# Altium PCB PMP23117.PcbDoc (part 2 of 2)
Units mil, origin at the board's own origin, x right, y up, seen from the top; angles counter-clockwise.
Board outline 3300 x 2800 mil, 6 copper layers (Top Layer, GND Layer 1, Signal Layer 1, GND Layer 2, Signal Layer3, Bottom Layer), stack 62.8 mil thick; 125 components, 38 nets, 250 pads, 683 vias.
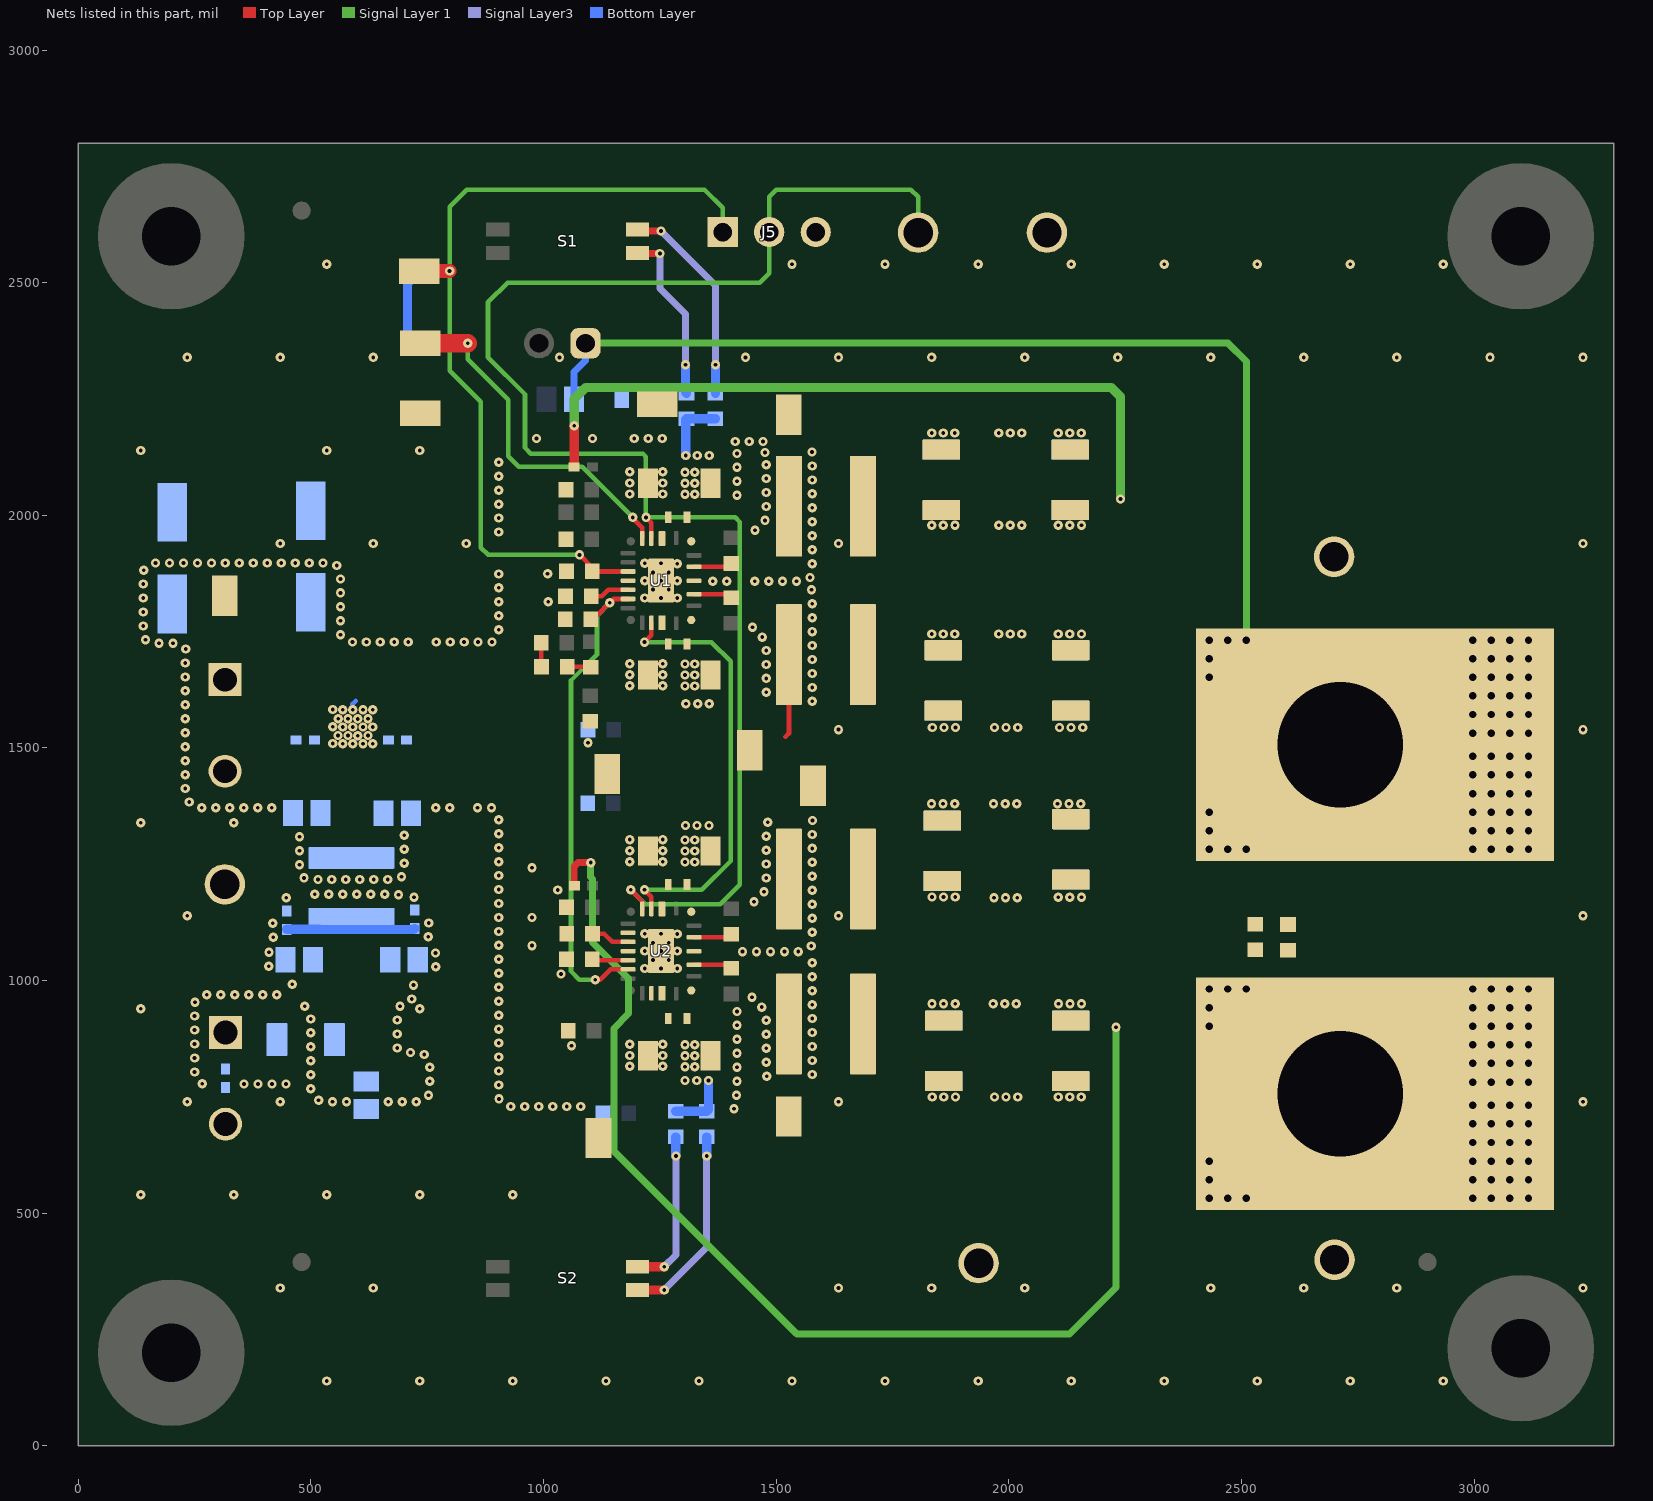
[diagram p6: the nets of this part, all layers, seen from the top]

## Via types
v1: diameter 20, hole 8, Top Layer to Bottom Layer, tented both sides, 561 vias
v2: diameter 32, hole 16, Top Layer to Bottom Layer, 116 vias
v3: diameter 19.68, hole 7.87, Top Layer to Bottom Layer, 6 vias

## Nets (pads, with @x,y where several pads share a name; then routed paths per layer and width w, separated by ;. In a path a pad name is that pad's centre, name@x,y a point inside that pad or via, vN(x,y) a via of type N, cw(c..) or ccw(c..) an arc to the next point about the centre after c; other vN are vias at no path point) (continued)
GND: C1.2 C2.2 C3.1 C4.1 C5.2 C6.2 C8.1 C9.1 C10.1 C11.1 C12.1 C13.2 C14.1 C15.1 C18.1 C19.1 C20.1 C21.1 C22.1 C23.2 C24.1 C25.1 C26.2 C27.1 C28.1 C29.2 C30.2 C32.1 C33.1 C34.1 C35.1 C36.1 C37.1 C38.1 C40.1 C45.2 C46.2 C47.2 C48.2 C49.2 C50.2 C51.2 C52.2 C53.2 C54.2 J1.2 J3.1 J5.3 J6.2 R6.1 R7.1 R10.1 R12.1 R14.1 R16.1 R17.1 R20.1 R23.1 T2.1 TP11.1 TP12.1 TP13.1 TP14.1 TP15.1 TP16.1 TP17.1 TP18.1 U1.4 U1.9 U1.16 U1.23 U1.25 U2.4 U2.9 U2.14 U2.16 U2.23 U2.25 | length 51.7
  Top Layer w10: C26.2@1050.61,1674.35 1100.66,1674.35 C24.1@1101.8,1673.2
  other v1: 534,139.5 734,139.5 934,139.5 1134,139.5 1334,139.5 1534,139.5 1734,139.5 1934,139.5 2134,139.5 2334,139.5 2534,139.5 2734,139.5 2934,139.5 434,339.5 634,339.5 1634,339.5 1834,339.5 2034,339.5 2434,339.5 2634,339.5 2834,339.5 3234,339.5 134,539.5 334,539.5 534,539.5 734,539.5 934,539.5 1409.2,724.28 929.63,729.61 959.63,729.61 989.63,729.61 1019.63,729.61 1049.63,729.61 1079.63,729.61 234,739.5 434,739.5 546.27,739.61 576.27,739.61 666.27,739.61 696.27,739.61 726.27,739.61 1634,739.5 3234,739.5 516.43,742.75 904.35,745.76 1835.55,750 1860.37,750 1885.37,750 1969.17,750 1994,750 2019,750 2106.11,750 2130.94,750 2155.94,750 752.7,753.8 1414.73,753.76 499.68,767.64 903.61,775.75 356.14,777.7 386.14,777.7 416.14,777.7 446.14,777.7 266.15,778.53 755.39,783.67 1415.89,783.74 1479.72,794.57 499.61,797.64 1577.19,798.36 249.91,803.75 903.61,805.75 755.39,813.67 1415.89,813.74 1185,815.65 1256.07,815.65 1478.57,824.55 499.61,827.64 1577.19,828.36 249.91,833.75 903.61,835.75 1185,839.13 1256.07,839.13 743.45,841.2 1415.89,843.74 713.75,845.39 1478.57,854.55 685.39,855.19 499.61,857.64 1577.19,858.36 1060,860.17 249.91,863.75 1185,863.05 1256.07,863.05 903.61,865.75 1415.89,873.74 1478.57,884.55 685.39,885.19 499.61,887.64 1577.19,888.36 249.91,893.75 903.61,895.75 1415.89,903.74 1478.57,914.55 685.39,915.19 499.61,917.64 1577.19,918.36 249.91,923.75 903.61,925.75 1415.89,933.74 134,939.5 734,939.5 1469.19,943.04 486.92,944.82 691.27,944.61 1577.19,948.36 250.82,953.74 903.61,955.75 716.67,960.57 1447.98,964.26 276.29,969.58 306.29,969.58 336.29,969.58 366.29,969.58 396.29,969.58 426.29,969.58 1577.19,978.36 903.61,985.75 720.39,990.34 459.61,992.01 1577.19,1008.36 1037.49,1014 903.61,1015.75 1217.22,1026.08 1287.22,1026.08 768.23,1029.78 409,1031 1577.19,1038.36 1235.22,1044.51 1269.22,1044.51 903.61,1045.75 767.86,1059.4 410,1061 1427.64,1062.34 1457.64,1062.34 1487.64,1062.34 1517.64,1062.34 1547.64,1062.34 1217.22,1063.48 1287.22,1063.48 1575.18,1074.24 903.61,1075.75 975,1075.23 1235.22,1081.25 1269.22,1081.25 418.84,1093.12 751.94,1094.02 1217.22,1100.88 1287.22,1100.01 1577.19,1104.18 903.61,1105.75 417.96,1123.11 753.23,1123.99 1577.19,1134.18 903.61,1135.75 975,1135.75 234,1139.5 1634,1139.5 3234,1139.5 1577.19,1164.18 903.61,1165.75 1452.41,1169.66 446.89,1178 721.43,1179.23 688.36,1184.62 508.37,1185.46 538.37,1185.39 568.37,1185.39 598.37,1185.39 628.37,1185.39 658.37,1185.39 1473.62,1190.87 1030.27,1194.79 1577.19,1194.18 903.61,1195.75 514.96,1217.32 544.96,1217.32 574.96,1217.32 604.96,1217.32 634.96,1217.32 664.96,1217.32 485.16,1220.77 1478.68,1220.44 694.4,1223.07 1577.19,1224.18 903.61,1225.75 975,1242.81 475.41,1249.14 1478.68,1250.44 700.71,1252.4 1577.19,1254.18 903.61,1255.75 1185,1255.65 1256.07,1255.65 475.41,1279.14 1185,1279.13 1256.07,1279.13 1478.68,1280.44 700.71,1282.4 1577.19,1284.18 903.61,1285.75 1185,1303.05 1256.07,1303.05 475.41,1309.14 1478.68,1310.44 700.71,1312.4 1577.19,1314.18 903.61,1315.75 134,1339.5 334,1339.5 1481.72,1340.29 1578,1344 903.61,1345.75 265.5,1371.46 295.5,1371.46 325.5,1371.46 355.5,1371.46 385.5,1371.46 415.5,1371.46 768.16,1371.46 798.16,1371.46 858.16,1371.46 888.16,1371.46 1833.69,1380 1858.51,1380 1883.51,1380 1967.17,1380 1992,1380 2017,1380 2104.69,1380 2129.51,1380 2154.51,1380 238.24,1383.99 229.61,1412.72 229.61,1442.72 229.61,1472.72 229.61,1502.72 1095.33,1511.21 229.61,1532.72 1634,1539.5 3234,1539.5 1835.69,1543.96 1860.51,1543.96 1885.51,1543.96 1969.17,1543.96 1994,1543.96 2019,1543.96 2108.79,1543.96 2133.62,1543.96 2158.62,1543.96 229.61,1562.72 229.61,1592.72 1577.19,1600.14 1478.68,1619.57 229.61,1622.72 1577.19,1630.14 1185,1633.93 1256.07,1633.93 1478.68,1649.57 229.61,1652.72 1185,1657.41 1256.07,1657.41 1577.19,1660.14 1478.68,1679.57 1185,1681.33 1256.07,1681.33 229.61,1682.72 1577.19,1690.14 1478.68,1709.57 230.77,1712.7 1577.19,1720.14 173.49,1725.28 203.49,1725.17 589.16,1727.82 619.16,1727.82 649.16,1727.82 679.16,1727.82 709.16,1727.82 769.16,1727.82 799.16,1727.82 829.16,1727.82 859.16,1727.82 889.16,1727.82 144.42,1732.72 1470.07,1738.31 563.48,1743.33 1577.19,1750.14 903.61,1754.11 1448.85,1759.52 139.41,1762.3 563.48,1773.33 1577.19,1780.14 903.61,1784.11 139.41,1792.3 563.48,1803.33 1577.19,1810.14 903.61,1814.11 1010.25,1814.35 139.41,1822.3 1217.22,1822.23 1287.22,1822.23 563.48,1833.33 1235.22,1840.66 1269.22,1840.66 1575.84,1840.11 903.61,1844.11 139.41,1852.3 1363.7,1858.49 1393.7,1858.49 1453.7,1858.49 1483.7,1858.49 1513.7,1858.49 1543.7,1858.49 1217.22,1859.63 1287.22,1859.63 563.48,1863.33 1572.6,1866.53 903.61,1874.11 1008.64,1874.25 1235.22,1877.4 1269.22,1877.4 140.38,1882.29 555.55,1892.27 1287.22,1896.16 1577.19,1896.18 166.06,1897.79 196.06,1897.79 226.06,1897.79 256.06,1897.79 286.06,1897.79 316.06,1897.79 346.06,1897.79 376.06,1897.79 406.06,1897.79 436.06,1897.79 466.06,1897.79 496.06,1897.79 526.06,1897.79 1217.22,1897.03 1577.19,1926.18 434,1939.5 634,1939.5 834,1939.5 1634,1939.5 3234,1939.5 1577.19,1956.18 903.61,1964.11 1454.55,1967.95 1577.19,1986.18 1475.77,1989.16 903.61,1994.11 1577.19,2016.18 1478.68,2019.02 903.61,2024.11 1415.89,2043.14 1185,2046.04 1256.07,2046.04 1577.19,2046.18 1478.68,2049.02 903.61,2054.11 1185,2069.53 1256.07,2069.53 1415.89,2073.14 1577.19,2076.18 1478.68,2079.02 903.61,2084.11 1185,2093.44 1256.07,2093.44 1415.89,2103.14 1577.19,2106.18 1478.68,2109.02 903.61,2114.11 1415.89,2133.14 1476,2135 1577,2136 134,2139.5 534,2139.5 734,2139.5 1411.79,2158.81 1441.79,2158.81 1471.79,2158.81 984.95,2165.25 1104.95,2165.25 1194.95,2165.25 1224.95,2165.25 1254.95,2165.25 1834.03,2177 1858.86,2177 1883.86,2177 1978.17,2177 2003,2177 2028,2177 2105.93,2177 2130.76,2177 2155.76,2177 234,2339.5 434,2339.5 634,2339.5 1034,2339.5 1434,2339.5 1634,2339.5 1834,2339.5 2034,2339.5 2234,2339.5 2434,2339.5 2634,2339.5 2834,2339.5 3034,2339.5 3234,2339.5 534,2539.5 1534,2539.5 1734,2539.5 1934,2539.5 2134,2539.5 2334,2539.5 2534,2539.5 2734,2539.5 2934,2539.5
  other v2: 2430.73,532 2470.73,532 2510.73,532 2997,532 3037,532 3077,532 3117,532 2430.73,572 2997,572 3037,572 3077,572 3117,572 2430.73,612 2997,612 3037,612 3077,612 3117,612 2997,652 3037,652 3077,652 3117,652 2997,692 3037,692 3077,692 3117,692 2997,732 3037,732 3077,732 3117,732 2997,782 3037,782 3077,782 3117,782 2997,822 3037,822 3077,822 3117,822 2997,862 3037,862 3077,862 3117,862 2430.73,902 2997,902 3037,902 3077,902 3117,902 2430.73,942 2997,942 3037,942 3077,942 3117,942 2430.73,982 2470.73,982 2510.73,982 2997,982 3037,982 3077,982 3117,982
  other v3: 1252.43,1026.08 1252.43,1063.48 1252.43,1100.88 1252.43,1822.23 1252.43,1859.63 1252.43,1897.03
MODE: J5.2 TP5.1 U1.10 U2.11 | length 3296.5
  Top Layer w10: v1@1182.41,1195.05 v1(1187.1,1195.05) 1212.07,1170.08 U2.11@1212.07,1154.03 ; v1@1226.8,1988.88 1231.76,1983.92 U1.10@1231.76,1950.18
  Signal Layer 1 w10: v1(1187.1,1195.05) 1218.28,1163.88 1380.03,1163.88 1421.88,1205.73 1421.88,1985.75 1412.02,1995.61 v1(1219.95,1995.61) 1219.95,2126 1213.71,2132.24 972.76,2132.24 960,2145 960,2260 880.39,2339.61 880.39,2457.89 922.51,2500 1464.79,2500 1484.95,2520.16 J5.2@1484.95,2608.88 1484.95,2684.95 1500,2700 1789.38,2700 1805,2684.38 TP5.1@1805,2607.75
NetC26_1: C26.1 R13.1 | length 52.1
  Top Layer w10: R13.1@994.76,1726.13 994.76,1675.08 C26.1@995.49,1674.35
NetR2_2: R2.2 S1.1 | length 372.7
  Top Layer w15: S1.1@1201.68,2564.19 1203.06,2562.8 v1(1250,2562.8)
  Signal Layer3 w15: v1(1250,2562.8) 1250,2487.43 1304.91,2432.51 v1(1304.91,2323.55)
  Bottom Layer w20: v1(1304.91,2323.55) 1304.91,2264.85 R2.2@1307.1,2262.67
NetR5_2: R5.2 S1.2 | length 449.1
  Top Layer w15: S1.2@1201.68,2614.19 1204.88,2610.99 v1(1252.43,2610.99)
  Signal Layer3 w15: v1(1252.43,2610.99) 1369.67,2493.74 v1(1369.67,2323.55)
  Bottom Layer w20: R5.2@1369.32,2262.67 1369.67,2263.02 v1(1369.67,2323.55)
NetR9_2: R9.2 S2.1 | length 424.5
  Top Layer w20: S2.1@1201.68,335 v1(1259.23,335)
  Signal Layer3 w15: v1(1259.23,335) 1350.42,426.19 v1(1350.42,622.81)
  Bottom Layer w20: v1(1350.42,622.81) 1350.42,663.7 R9.2@1350.73,664.02
NetR11_2: R11.2 S2.2 | length 347.1
  Top Layer w20: S2.2@1201.68,385 v1(1259.23,385)
  Signal Layer3 w15: v1(1259.23,385) 1284.42,410.19 v1(1284.42,622.81)
  Bottom Layer w20: R11.2@1284.29,664.02 1284.29,622.95 v1(1284.42,622.81)
PG1_P: R8.2 TP10.1 U1.11 | length 801.7
  Top Layer w10: v1(1191.8,1995.61) 1191.8,1994.05 1212.07,1973.78 U1.11@1212.07,1950.18
  Top Layer w40: TP10.1@765,2370 v1(837.27,2370)
  Signal Layer 1 w10: v1(837.27,2370) 837.27,2335.24 924,2248.51 924,2127.49 946.87,2104.63 1082.77,2104.63 v1(1191.8,1995.61)
  Bottom Layer w20: R8.2@762.55,2370 v1(837.27,2370)
RT_P: R10.2 U1.17 | length 85
  Top Layer w10: R10.2@1102.35,1825.93 1125.1,1825.93 1139.12,1839.94 U1.17@1181.56,1839.94
RT_S: R16.2 U2.17 | length 77.8
  Top Layer w10: R16.2@1104.36,1042.29 1105.86,1043.8 U2.17@1181.56,1043.8
SS: C25.2 U1.18 U2.18 | length 1064.5
  Top Layer w10: C25.2@1101.51,1776.95 1106.52,1776.95 1149.83,1820.26 U1.18@1181.56,1820.26 ; v1(1111.25,1001.68) 1121.54,1001.68 1143.97,1024.11 U2.18@1181.56,1024.11
  Signal Layer 1 w10: v1(1111.25,1001.68) 1076.98,1001.68 1058.89,1019.76 1058.89,1645 1114.91,1701.01 1114.91,1784.67 v1(1142.47,1812.23)
SW1: C7.2 L1.1 TP2.1 U1.5 | length 102.5
  Top Layer w10: U1.5@1323.29,1889.16 1396.84,1889.16 C7.2@1403.18,1895.49 ; TP2.1@1513.24,2206.76 TP2.1@1527.39,2192.61
SW2: C17.1 L2.1 TP4.1 U1.3 | length 262.7
  Top Layer w10: U1.3@1323.29,1830.1 1396.29,1830.1 C17.1@1403.18,1823.21 ; 1520,1523.88 1527.39,1531.26 L2.1@1527.39,1700.76
SW3: C31.1 L3.1 TP6.1 U2.5 | length 81.3
  Top Layer w10: U2.5@1323.29,1093.01 1399.87,1093.01 C31.1@1403.18,1096.32
SW4: C39.2 L4.1 TP8.1 U2.3 | length 107.4
  Top Layer w10: U2.3@1323.29,1033.95 1395.66,1033.95 C39.2@1403.18,1026.44 ; TP8.1@1510,708.57 TP8.1@1527.27,725.84
SYNCOUT: U1.22 U2.10 | length 937.4
  Top Layer w10: v1(1216.8,1195.05) 1231.76,1180.09 U2.10@1231.76,1154.03 ; v1(1217.04,1727.58) 1231.76,1742.3 U1.22@1231.76,1769.08
  Signal Layer 1 w10: v1(1216.8,1195.05) 1340,1195.05 1402,1257.05 1402,1686.34 1360.76,1727.58 v1(1217.04,1727.58) v1@1216.8,1727.34
SYNCOUT_S: U2.22
VCC_P: C15.2 J5.1 R8.1 TP7.1 U1.15 | length 2068.5
  Top Layer w10: v1(1077.3,1915) 1104.36,1887.94 C15.2@1104.36,1880.26 1105.3,1879.31 U1.15@1181.56,1879.31
  Top Layer w30: TP7.1@733.04,2525 v1(798,2525)
  Signal Layer 1 w10: v1(1077.3,1915) 880.62,1915 865,1930.62 865,2244 798,2311 v1(798,2525) 798,2663 835,2700 1345.93,2700 1384.95,2660.98 J5.1@1384.95,2608.88
  Bottom Layer w20: R8.1@707.44,2370 707.44,2499.4 733.04,2525 v1(798,2525)
VCC_S: C38.2 U2.15 | length 83.7
  Top Layer w10: C38.2@1105.15,1100.88 1129.79,1100.88 1147.51,1083.17 U2.15@1181.56,1083.17
VIN: C1.1 C2.1 C3.2 C4.2 C5.1 C6.1 C27.2 C28.2 C29.1 C30.1 C51.1 C52.1 C53.1 C54.1 J1.1 L5.2 R2.1 R5.1 R9.1 R11.1 TP1.1 U1.1 U1.7 U2.1 U2.7 | length 292.4
  Bottom Layer w10: J1.1@315.37,1646.85 J1.1@320,1651.48 ; 589,1594 596,1601
  Bottom Layer w20: R11.1@1284.29,719.13 R9.1@1350.73,719.13 1354.44,722.84 v1(1354.44,785.14) ; v1(1305.41,2128.48) 1305.41,2205.86 R2.1@1307.1,2207.55 R5.1@1369.32,2207.55
  other v1: 1303.94,785.14 1329.44,785.14 1303.94,815 1325,815 1303.94,838.48 1325,838.48 1303.94,862.4 1325,862.4 1303.94,1255 1325,1255 1303.94,1278.48 1325,1278.48 1303.94,1302.4 1325,1302.4 1304.91,1333.48 1329.91,1333.48 1355.41,1333.48 546.98,1509.5 568.5,1509 590,1509 611.87,1509 633,1509 600.5,1526.5 558.12,1527 579.5,1527 622.5,1527 546.98,1545.5 568.5,1545 590,1545 611.87,1545 633,1545 600.75,1562.5 558.37,1563 579.75,1563 622.75,1563 568.5,1582 590,1582 611.87,1582 633,1582 546.98,1582.5 1305.86,1595 1331.36,1595 1356.36,1595 1303.94,1633.28 1325,1633.28 1303.94,1656.76 1325,1656.76 1303.94,1680.68 1325,1680.68 1303.94,2045.39 1325,2045.39 1303.94,2068.88 1325,2068.88 1303.94,2092.8 1325,2092.8 1330.41,2128.48 1355.91,2128.48
VIN_EMI: C45.1 FB2.1 J6.1
VINEMI2: C46.1 C47.1 C48.1 C49.1 C50.1 FB2.2 L5.1 | length 276
  Bottom Layer w20: C48.1@448,1110.32 517.68,1110.32 518,1110 721,1110 C47.1@723,1112
VOUT: C8.2 C9.2 C10.2 C11.2 C12.2 C13.1 C18.2 C19.2 C20.2 C21.2 C22.2 C23.1 C32.2 C33.2 C34.2 C35.2 C36.2 C40.2 J2.1 J4.1 L1.2 L2.2 L3.2 L4.2 R1.2 R4.2 R15.1 T1.1 TP3.1 | length 6314.6
  Top Layer w15: R15.1@1065.92,1203.88 1065.92,1245.6 1073.95,1253.62 v1(1101.18,1253.62)
  Top Layer w20: R1.2@1065.92,2104.87 v1(1065.92,2192.61)
  Signal Layer 1 w15: J4.1@1090.05,2370 2471,2370 2510.53,2330.47 T1.1@2510.53,1732.4 ; v1(1101.18,1253.62) 1101.18,1222.72 1105.29,1218.61 1105.29,1081.71 1182.78,1004.23 1182.78,929.11 1150.93,897.26 1150.93,633.24 1544.17,240 2130.42,240 2230.42,340 v1(2230.42,900)
  Signal Layer 1 w20: v1(1065.92,2192.61) 1065.92,2250.36 1090.56,2275 2219.92,2275 2240,2254.92 v1(2240,2035.23)
  Bottom Layer w15: R4.2@1065.37,2249.81 1065.37,2307.88 1090.05,2332.56 J4.1@1090.05,2370
  other v1: 1834.78,950 1859.61,950 1884.61,950 1966.17,950 1991,950 2016,950 2106.54,950 2131.37,950 2156.37,950 1968.17,1178 1993,1178 2018,1178 1834.9,1179.75 1859.73,1179.75 1884.73,1179.75 2106.17,1179.23 2131,1179.23 2156,1179.23 1834.02,1745 1858.85,1745 1883.85,1745 1978.17,1745 2003,1745 2028,1745 2106.17,1745 2131,1745 2156,1745 1834.27,1979 1859.1,1979 1884.1,1979 1978.17,1979 2003,1979 2028,1979 2106.17,1979 2131,1979 2156,1979
  other v2: 2430.73,1282 2470.73,1282 2510.73,1282 2997,1282 3037,1282 3077,1282 3117,1282 2430.73,1322 2997,1322 3037,1322 3077,1322 3117,1322 2430.73,1362 2997,1362 3037,1362 3077,1362 3117,1362 2997,1402 3037,1402 3077,1402 3117,1402 2997,1442 3037,1442 3077,1442 3117,1442 2997,1482 3037,1482 3077,1482 3117,1482 2997,1532 3037,1532 3077,1532 3117,1532 2997,1572 3037,1572 3077,1572 3117,1572 2997,1612 3037,1612 3077,1612 3117,1612 2430.73,1652 2997,1652 3037,1652 3077,1652 3117,1652 2430.73,1692 2997,1692 3037,1692 3077,1692 3117,1692 2430.73,1732 2470.73,1732 2510.73,1732 2997,1732 3037,1732 3077,1732 3117,1732
pads on no net: FID1.1 FID2.1 FID3.1 H1.1 H2.1 H3.1 H4.1 H5.0 H6.0 H7.0 H8.0 SH-J1.0 U1.8 U1.24 U2.8 U2.24
copper on no net: | length 0.7
  Bottom Layer w10: 1287.17,1539.5 1287.67,1540

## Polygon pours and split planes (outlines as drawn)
GND on Top Layer "TOP_LAYER_GND_P405" (solid, remove dead copper, pour order 405): 0,2800 3300,2800 3300,0 0,0
VOUT on Top Layer "TOP_LAYER_VOUT_P389" (solid, remove dead copper, pour order 389): 2150.06,1666.26 2186.05,1666.26 cw(c2186.05,1625.51) 2226.8,1625.51 2286.01,1625.51 ccw(c2286.01,1626.3) 2286.8,1626.3 2286.8,1701.63 2150.06,1701.63
VOUT on Top Layer "TOP_LAYER_VOUT_P381" (solid, remove dead copper, pour order 381): 2227.47,2056.57 3125.37,2056.57 cw(c3125.37,1983.88) 3198.07,1983.88 3198.07,1166.98 cw(c3110.85,1182.25) 3095.57,1095.03 2421.27,1095.03 ccw(c2453.17,953.14) 2310,927.62 cw(c2245.75,934.36) 2238.99,870.11 2226.8,870.11
VOUT on Top Layer "TOP_LAYER_VOUT_P387" (solid, remove dead copper, pour order 387): 1656.8,1332.73 1751.8,1332.73 1751.8,1267.73 1759.1,1260.43 2262,1260.43 2262,870.11 1761.85,870.11 1751.8,860.17 1751.8,795.9 1656.8,795.9
VOUT on Top Layer "TOP_LAYER_VOUT_P379" (solid, remove dead copper, pour order 379): 1656.8,2128.88 1751.8,2128.88 1751.8,2063.88 1759.1,2056.57 2286,2056.57 2286,1666.26 1761.85,1666.26 1751.8,1656.31 1751.8,1592.05 1656.8,1592.05
SW4 on Top Layer "TOP_LAYER_SW4_P369" (solid, remove dead copper, pour order 369): 1305.65,1046.75 1556.8,1046.75 1556.8,797.73 1499.8,797.73 1499.8,941.27 1428.34,1012.73 1378.38,1012.73 1363.38,1027.73 1305.65,1027.73
SW3 on Top Layer "TOP_LAYER_SW3_P367" (solid, remove dead copper, pour order 367): 1305.65,1082.73 1556.8,1082.73 1556.8,1331.35 1499.8,1331.35 1499.8,1188.21 1428.34,1116.75 1378.38,1116.75 1363.38,1101.75 1305.65,1101.75
SW1 on Top Layer "TOP_LAYER_SW1_P365" (solid, remove dead copper, pour order 365): 1305.65,1878.88 1556.8,1878.88 1556.8,2127.49 1499.8,2127.49 1499.8,1984.36 1428.34,1912.9 1378.38,1912.9 1363.38,1897.9 1305.65,1897.9
SW2 on Top Layer "TOP_LAYER_SW2_P359" (solid, remove dead copper, pour order 359): 1305.65,1842.9 1556.8,1842.9 1556.8,1593.88 1499.8,1593.88 1499.8,1737.42 1428.34,1808.88 1378.38,1808.88 1363.38,1823.88 1305.65,1823.88
VIN on Top Layer "TOP_LAYER_VIN_P357" (solid, remove dead copper, pour order 357): 1339.41,1139.25 1339.41,1190.28 1395.5,1246.37 1395.5,1348.72 1292.84,1348.72 1292.84,1185.82 1307.55,1171.12 1307.55,1139.22
VIN on Top Layer "TOP_LAYER_VIN_P355" (solid, remove dead copper, pour order 355): 1339.16,988.1 1339.15,937.08 1395.25,880.99 1395.25,770 1292.59,770 1292.59,941.53 1307.29,956.24 1307.29,988.14
VIN on Top Layer "TOP_LAYER_VIN_P351" (solid, remove dead copper, pour order 351): 1339.16,1784.25 1339.15,1733.22 1395.25,1677.14 1395.25,1574.79 1292.59,1574.79 1292.59,1737.68 1307.29,1752.39 1307.29,1784.28
VIN on Top Layer "TOP_LAYER_VIN_P347" (solid, remove dead copper, pour order 347): 1339.41,1935.4 1339.41,1986.42 1395.5,2042.51 1395.5,2144.86 1292.84,2144.86 1292.84,1981.97 1307.55,1967.26 1307.55,1935.37
GND on Bottom Layer "BOTTOM_LAYER_GND_P449" (solid, remove dead copper, pour order 449): 0,2800 3300,2800 3300,0 0,0
VIN on Bottom Layer "BOTTOM_LAYER_VIN_P443" (solid, remove dead copper, pour order 443): 282.56,1745.28 282.56,1610 350.69,1610 350.69,1742.45 382.83,1742.45 543.09,1742.45 543.09,1876.11 541.8,1877.4 159.8,1877.4 159.8,1745.73
VINEMI2 on Bottom Layer "BOTTOM_LAYER_VINEMI2_P441" (solid, remove dead copper, pour order 441): 490,1160 ccw(c502.8,1140.56) 480,1145.25 480,980 ccw(c492.07,992.07) 492.07,975 700,975 700,1147.93 ccw(c682.94,1147.93) 695,1160 ccw(c682.93,1147.94) 682.93,1165 510,1165 ccw(c506.03,1138.37)
VINEMI2 on Bottom Layer "BOTTOM_LAYER_VINEMI2_P435" (solid, remove dead copper, pour order 435): 480,1000 480,975 ccw(c490,975) 490,965 510,965 cw(c510,955) 520,955 520,770 ccw(c530,770) 530,760 730,760 ccw(c730,765) 735,765 735,820 ccw(c730,820) 730,825 675,825 cw(c675,835) 665,835 665,955 cw(c675,955) 675,965 690,965 ccw(c690,975) 700,975 700,1000
VIN on Bottom Layer "BOTTOM_LAYER_VIN_P429" (solid, remove dead copper, pour order 429): 495.8,1609 495.8,1237.71 680.31,1237.71 680.31,1609
GND on GND Layer 1 "GND_LAYER_1_GND_P445" (solid, remove dead copper, pour order 445): 0,2800 3300,2800 3300,0 0,0
GND on Signal Layer3 "SIGNAL_LAYER3_GND_P451" (solid, remove dead copper, pour order 451): 0,2800 3300,2800 3300,0 0,0
VOUT on Signal Layer3 "SIGNAL_LAYER3_VOUT_P415" (solid, remove dead copper, pour order 415): 1656.8,2193.8 3198.07,2193.8 3198.07,841.48 3198.07,440 1656.8,440
VIN on Signal Layer3 "SIGNAL_LAYER3_VIN_P409" (solid, remove dead copper, pour order 409): 250,1707.43 924,1707.43 924,2144.86 1292.84,2144.86 1395.5,2144.86 1395.5,750 924,750 924,1391.85 250,1391.85
GND on GND Layer 2 "GND_LAYER_2_GND_P447" (solid, remove dead copper, pour order 447): 0,2800 3300,2800 3300,0 0,0
GND on Signal Layer 1 "SIGNAL_LAYER_1_GND_P453" (solid, remove dead copper, pour order 453): 0,2800 3300,2800 3300,0 0,0

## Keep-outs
Keep-Out Layer:
  text ".Layer_Name" at 237.5,-1045.49 h60

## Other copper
Top Layer:
  region net VIN: 281,1656 281,1870 351,1870 351,1657 352,1656
  region net SW4: 1499,834 1499,724 1555,724 1555,834
  region net SW3: 1550,1462 1500,1412 1500,1304 1557,1304 1557,1366 1567,1376 1605,1376 1605,1462
  region net SW2: 1452,1538 1472,1538 1500,1566 1500,1613 1556,1613 1557,1614 1557,1538 1471,1452 1452,1452
  region net SW1: 1499,2110 1499,2259 1557,2259 1557,2110
  region net SW1: 1500,2100
  region: 1499,2123
  region net EN1: 1167.59,1934.43 1167.59,1965.93 1193.26,1965.93 1193.11,1934.43
  region net EN4: 1167.59,957.18 1167.59,988.68 1195.9,988.68 1195.75,957.18
  region net EN3: 1167.59,1138.29 1167.59,1169.78 1193.26,1169.78 1193.11,1138.29
  region net COMP: 1043.97,1740 1107.26,1740 1107.26,1713.45 1043.97,1713.45
  region: 1039.51,1735.57
  pour cut-out: 1303.94,1138.59 1338.96,1138.59 1339.17,1103.16 1303.94,1103.16
  pour cut-out: 1339.16,988.1 1305.86,988.1 1305.65,1024.01 1339.16,1024.01
  pour cut-out: 1339.16,1784.25 1305.86,1784.25 1305.65,1820.16 1339.16,1820.16
  pour cut-out: 1303.94,1934.73 1338.96,1934.73 1339.17,1899.3 1303.94,1899.3
  text ".Layer_Name" at 237.5,-1045.49 h60
Signal Layer 1:
  region: 3150.86,2986.6
Bottom Layer:
  region net VOUT: 2186.11,880.99 2186.11,955.02 1800,955.02 1800,880.99
  region net VOUT: 1795,1249.8 1795,1170 2186.11,1170 2186.11,1249.8
  region net VIN_EMI: 270.3,949.19 270.3,798.1 454.17,798.1 454.17,949.19
  region net VOUT: 1803.5,2045 1803.5,1970 2184.95,1970 2184.95,2045
  region net VOUT: 1803.5,1752.14 1803.5,1677.14 2186.11,1677.14 2186.11,1752.14
  region: 164,1875
  text ".Layer_Name" at 237.5,-1045.49 h60

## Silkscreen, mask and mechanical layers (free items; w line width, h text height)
Top Overlay:
  circle w10: c1200.36,290 r4.4
  circle w10: c1202.91,2524.39 r4.4
  lines w10: 526,1705.46 574,1705.46 ; 531.67,937.5 579.67,937.5 ; 547,1342.46 547,1392.96 ; 551,1682.96 551,1729.46 ; 552.67,574.5 552.67,625 ; 556.67,915 556.67,961.5 ; 987.95,1619.12 1045.03,1619.12 1073.99,1648.08
  text "EN2" at 827.85,2668.19 h35 r359.65
  text ".PRJ_Number" at 2379,2522 h100
  text "FPWM" at 1327.23,2508.88 h35 r0.82
  text "PFM" at 1540,2508.88 h35 r0.82
  text "EN1" at 827.85,2445 h35 r359.65
  text "LMQ644A2Q" at 2380,2440 h80
  text "A" at 975.81,2432.72 h54 r0.82
  text "B" at 1077.3,2432.72 h54 r0.82
  text "4-Phase Buck Converter" at 2360,2320 h72
  text "V      = 3.8V to 16V" at 2370.5,2292 h63
  text "IN" at 2413,2285 h32
  text "V      = 3.3V" at 2370.5,2227 h63
  text "OUT1" at 2412.5,2221.09 h32
  text "F      = 500 kHz" at 2377.48,2158 h63
  text "SW" at 2419.48,2151 h32
  text "I       = 24 A" at 2380,2090 h63
  text "OUT" at 2412.5,2081.09 h32
  text "VIN" at 398,1761 h72.83
  text "VIN_EMI" at 215,503 h72.83
  text "EN4" at 742.5,388.36 h35 r359.65
  text "EN3" at 737.84,246.48 h35 r359.65
  text ".Layer_Name" at 237.5,-1045.49 h60
Bottom Overlay:
  text ".Layer_Name" at 237.5,-1045.49 h60
Top Paste:
  text ".Layer_Name" at 237.5,-1045.49 h60
Bottom Paste:
  text ".Layer_Name" at 237.5,-1045.49 h60
Top Solder:
  text ".Layer_Name" at 237.5,-1045.49 h60
  text ".Layer_Name" at 237.5,-1045.49 h60
Bottom Solder:
  rectangle: 565,816.1 620,938.1
  rectangle: 370.43,816.1 430,934.39
  text ".Layer_Name" at 237.5,-1045.49 h60
Drill Guide:
  text ".Layer_Name" at 237.5,-1045.49 h60
M1 Board Outline:
  the board outline again, w10
M2 Board Dimensions:
  rectangle: -339.5,-462 -214.5,-337
  rectangle: -214.5,-587 160.5,-462
  lines w7: -339.5,-462 660.5,-462 ; -214.5,-587 -214.5,-337 ; -89.5,-587 -89.5,-337 ; 160.5,-587 160.5,-337 ; 410.5,-587 410.5,-337 ; -339.5,-587 660.5,-587 660.5,-337 -339.5,-337 -339.5,-587
  text ".Layer_Name" at 237.5,-1045.49 h60
M3 3D STEP Top:
  text ".Layer_Name" at 237.5,-1045.49 h60
M4 3D STEP Bottom:
  text ".Layer_Name" at 237.5,-1045.49 h60
M5 Assembly Top:
  lines w10: -631.5,-1117.17 5968.5,-1117.17 ; -631.5,-913.83 5970.5,-913.83 ; -631.5,-710.5 -631.5,-1320.5 3373.5,-1320.5 5970.5,-1320.5 5970.5,-710.5 -631,-710.5 -631,-1320.5 944.5,-1320.5 ; 1833.5,-1320.5 1833.5,-710.5 ; 3100.5,-913.83 3100.5,-710.5 ; 3940.5,-913.83 3940.5,-710.5 ; 4562.5,-1327 4562.5,-1124.17
  text "COMPONENTS MARKED 'DNP' SHOULD NOT BE POPULATED." at 814,-505.5 h60
  text "ASSEMBLY VARIANT:" at 813.5,-621 h60
  text ".VariantName" at 1849.5,-621 h60
  text "PCB VIEWED FROM TOP SIDE" at -568,-842.67 h60
  text "BOARD #:" at 1908.5,-842.67 h60
  text ".PRJ_Number" at 2454,-842.67 h60
  text "REV:" at 3298.5,-842.67 h60
  text ".PCB_Rev" at 3590,-842.67 h60
  text "SVN REV:" at 4136.5,-842.67 h60
  text ".VersionControl_RevNumber" at 4642.5,-842.67 h60
  text "TID #:" at 1908.5,-1046 h60
  text ".TID" at 2454,-1046 h60
  text "PLOT NAME =" at -568,-1251.34 h60
  text ".plot_File_Name" at 237.5,-1251.34 h60
  text "GENERATED    :" at 1910.5,-1251.34 h60
  text ".Print_Date" at 2780,-1251.34 h60
  text ".Print_Time" at 3509,-1251.34 h60
  text "TEXAS INSTRUMENTS" at 4773.5,-1251.34 h60
M6 Assembly Bottom:
  lines w10: -632,-914.33 5970,-914.33 ; -630,-1117.67 5970,-1117.67 ; 776,-1327.5 776,-1124.67 ; 1398,-914.33 1398,-711 ; 2238,-914.33 2238,-711 ; 3505,-1321 3505,-711 ; 4394,-1321 5969.5,-1321 5969.5,-711 -632,-711 -632,-1321 1965,-1321 5970,-1321 5970,-711
  text "COMPONENTS MARKED 'DNP' SHOULD NOT BE POPULATED." at 5762.5,-505 h60
  text ".VariantName" at 4718.5,-621 h60
  text "ASSEMBLY VARIANT:" at 5757.5,-621 h60
  text ".VersionControl_RevNumber" at 696,-843.17 h60
  text "SVN REV:" at 1202,-843.17 h60
  text ".PCB_Rev" at 1748.5,-843.17 h60
  text "REV:" at 2040,-843.17 h60
  text ".PRJ_Number" at 2884.5,-843.17 h60
  text "BOARD #:" at 3430,-843.17 h60
  text "PCB VIEWED FROM BOTTOM SIDE" at 5906.5,-843.17 h60
  text ".TID" at 2884.5,-1046.5 h60
  text "TID #:" at 3430,-1046.5 h60
  text "TEXAS INSTRUMENTS" at 565,-1251.84 h60
  text ".Print_Time" at 1829.5,-1251.84 h60
  text ".Print_Date" at 2558.5,-1251.84 h60
  text "GENERATED    :" at 3428,-1251.84 h60
  text ".plot_File_Name" at 5101,-1251.84 h60
  text "PLOT NAME =" at 5906.5,-1251.84 h60
M9 Title Sheet:
  drawing of 57 lines, arcs and shapes, not listed
  text "1" at 400.34,7849.5 h70
  text "2" at 2896,7849.5 h70
  text "3" at 5385.34,7849.5 h70
  text "4" at 7892.01,7849.5 h70
  text "5" at 10391,7849.5 h70
  text "6" at 12896,7849.5 h70
  text "A" at -756,6706.5 h70
  text "A" at 14044,6706.5 h70
  text "B" at -756,4326.5 h70
  text "B" at 14044,4326.5 h70
  text "C" at -756,1951.5 h70
  text "C" at 14044,1951.5 h70
  text "PROJECT TITLE:" at 11004,90.5 h45
  text ".PRJ_Title" at 11054,-42.83 h70
  text "DESIGNED FOR:" at 11004,-210.5 h45
  text ".PRJ_Customer" at 11054,-350.5 h70
  text "D" at -756,-418.5 h70
  text "D" at 14044,-418.5 h70
  text "FILE NAME:" at 11004,-510.5 h45
  text ".PCB_File_Name_No_Path" at 11054,-630.5 h70
  text "Texas Instruments (TI) and/or its licensors do not warrant the accuracy or completeness of this specification" at 6034.5,-792.34 h45
  text "ENGINEER:" at 11004,-800.5 h45
  text "LAYOUT BY:" at 12509,-800.5 h45
  text "or any information contained therein. TI and/or its licensors do not warrant that this design will meet" at 5989.51,-905 h45
  text ".PRJ_Engineer" at 11054,-955.49 h70
  text ".PCB_Layout" at 12559.5,-955.49 h70
  text "the specifications, will be suitable for your application or fit for any particular purpose, or will operate in" at 5989.51,-1017.67 h45
  text ".Layer_Name" at 237.5,-1045.49 h60
  text "ALTIUM DESIGNER VERSION:" at 12509,-1110.5 h45
  text "an implementation. TI and/or its licensors do not warrant that the design is production worthy. You should" at 5989.51,-1130.33 h45
  text "completely validate and test your design implementation to confirm the system functionality for your application." at 6034.5,-1243 h45
  text ".print_Scale" at 11054,-1243.83 h70
  text ".Application_BuildNumber" at 12559.5,-1243.83 h70
  text "1" at 400.34,-1450.5 h70
  text "2" at 2896,-1450.5 h70
  text "3" at 5385.34,-1450.5 h70
  text "4" at 7892.01,-1450.5 h70
  text "5" at 10391,-1450.5 h70
  text "6" at 12896,-1450.5 h70
M10 Fab Notes:
  drawing of 189 lines, arcs and shapes, not listed
  text "DESIGN INFORMATION" at 12042.52,6169.17 h60
  text "MIN. TRACK WIDTH:" at 11397.96,6037.05 h60
  text "8" at 12494.2,6037.05 h60
  text "MIL" at 12648.96,6037.05 h60
  text "MIN. CLEARANCE:" at 11397.96,5912.92 h60
  text "0.2" at 12434.2,5912.93 h60
  text "mm" at 12648.96,5912.92 h60
  text "MIN. VIA PAD SIZE:" at 11397.96,5788.8 h60
  text "20" at 12464.21,5788.8 h60
  text "MIL" at 12648.96,5788.8 h60
  text "0.05mm (2MIL)" at 12092.96,5658.9 h60
  text "MINIMUM ANNULAR RING" at 11068.73,5650.67 h60
  text "EXTERNAL" at 12800.96,5650.67 h60
  text "PER" at 11268.73,5540.55 h60
  text "IPC-D-275 CLASS 2 LEVEL C" at 11488.73,5540.54 h60
  text "MIL, HOLES" at 12976.96,5440.07 h60
  text "+/-" at 12584.5,5431.48 h60
  text "+/-" at 13438.5,5431.48 h60
  text "REGISTRATION TOLERANCES:" at 11068.73,5430.42 h60
  text "METAL" at 12268.5,5430.42 h60
  text "5" at 12844.7,5430.42 h60
  text "3" at 13677.7,5430.42 h60
  text "MIL" at 13793.96,5430.42 h60
  text "HOLE SIZE TOLERANCE (UNLESS OTHERWISE SPECIFIED):" at 11068.73,5332.1 h60
  text "+/-" at 13438.5,5329.23 h60
  text "3" at 13677.7,5328.17 h60
  text "MIL" at 13793.96,5328.17 h60
  text "MATERIAL:" at 10993.96,5190.52 h60
  text "FR-4 High Tg" at 11980.4,5062 h60
  text "X" at 11841,5056 h60
  text "FR-408" at 11414.96,5049.49 h60
  text "OTHER" at 12902.96,5049.49 h60
  text "62 MIL (1.6mm) +/-10%" at 11735.06,4906.46 h60
  text "X" at 11614.96,4904.01 h60
  text "THICKNESS:" at 11068.73,4898.24 h60
  text "OTHER" at 13019.96,4898.24 h60
  text "TOLERANCE:" at 11068.73,4759.92 h60
  text "X" at 11916.96,4759.92 h60
  text "ANSI IPC-6012 TYPE 3 CLASS 2" at 12094.98,4759.92 h60
  text "OTHER +/-" at 12094.96,4615.73 h60
  text "BOW & TWIST:" at 11068.73,4470.54 h60
  text "X" at 11916.96,4470.54 h60
  text "ANSI IPC-6012 TYPE 3 CLASS 2" at 12094.98,4470.54 h60
  text "OTHER +/-" at 12094.96,4323.85 h60
  text "DRILLING:" at 10993.96,4193.23 h60
  text "NC_DRILL FILES" at 12754.96,4088.04 h60
  text "REFERENCE:" at 11068.73,4084.1 h60
  text "X" at 11725.96,4084.01 h60
  text "AS SHOWN" at 11903.96,4084.1 h60
  text "X" at 12626.96,4084.1 h60
  text "OTHER" at 13052.96,3941.85 h60
  text "PTH COPPER THICKNESS:" at 11068.41,3938.32 h60
  text "X" at 12207.64,3938.32 h60
  text "20-30 um" at 12335.64,3938.32 h60
  text "BOARD FINISH:" at 10993.96,3790.73 h60
  text "SILKSCREEN:" at 11149.18,3680.6 h60
  text "X" at 12106.96,3680.6 h60
  text "TOP" at 12223.96,3680.6 h60
  text "X" at 12616.96,3680.6 h60
  text "BOTTOM" at 12734.96,3680.6 h60
  text "SILKSCREEN COLOR:" at 11149.18,3525.41 h60
  text "X" at 12105.96,3525.41 h60
  text "WHITE" at 12223.96,3525.41 h60
  text "OTHER" at 12734.96,3525.41 h60
  text "X" at 12236.96,3381.96 h60
  text "GREEN" at 12354.96,3381.96 h60
  text "OTHER" at 12972.96,3381.96 h60
  text "SOLDER RESIST COLOR:" at 11149.18,3375.1 h60
  text "X" at 12236.96,3227.71 h60
  text "MATTE" at 12354.96,3227.71 h60
  text "SEMI-GLOSS" at 12972.5,3227.07 h60
  text "IMMERSION GOLD (ENIG)" at 12054.96,3054.94 h60
  text "ENEPIG" at 13392.5,3047.72 h60
  text "SURFACE FINISH:" at 10993.96,3046.72 h60
  text "X" at 11876.96,3046.72 h60
  text "IMM. TIN/SILVER OR EQUIV" at 11323.5,2909.4 h60
  text "OTHER" at 12754.96,2905.47 h60
  text "ARRAY/PANEL:" at 10993.96,2750.09 h60
  text "X" at 11880,2741.87 h60
  text "CUT AND TRIM PER M1 BOARD OUTLINE" at 12054.96,2741.87 h60
  text "N.C. ROUTE" at 12054.96,2605.9 h60
  text "V. SCORE" at 12920.96,2605.9 h60
  text "CERTIFICATION:" at 10993.96,2476.77 h60
  text "MATERIALS AND WORKMANSHIP FOR ALL PCBS" at 11718.96,2476.77 h60
  text "TO MEET OR EXCEED THE REQUIREMENTS OF:" at 11718.96,2382.71 h60
  text "X" at 11356.47,2254.08 h60
  text "ANSI IPC-A-600F CLASS ->" at 11484.46,2254.08 h60
  text "X" at 13132.47,2254.08 h60
  text "2" at 13242.46,2254.08 h60
  text "1" at 12927.46,2252.58 h60
  text "3" at 13596.46,2252.58 h60
  text "X" at 12168.47,2106.39 h60
  text "RoHS" at 12296.46,2106.39 h60
  text "OTHER" at 12940.86,2106.39 h60
  text "PER ORDER" at 13337.92,2106.39 h60
  text "ALL BOARDS MUST MEET OR EXCEED UL94-V0 REQUIREMENTS." at 11021.5,1952.57 h60
  text "PCB MUST BEAR THE UL94V-0 UL REGISTERED MATERIAL ID NUMBER" at 11021.5,1836.5 h60
  text "ADDITIONAL REQUIREMENTS:" at 10993.96,1667.08 h60
  text "MICROSECTION:" at 11068.73,1559.95 h60
  text "YES" at 11974.46,1559.95 h60
  text "REQUIRED" at 12835.96,1415.62 h60
  text "BARE BOARD ELEC. TEST:" at 11068.73,1412.76 h60
  text "NONE" at 12374.46,1412.76 h60
  text "X" at 12717.96,1412.76 h60
  text "PER ORDER" at 13427.96,1412.76 h60
  text "XX MIL VIAS REQUIRE NON-CONDUCTIVE FILL AND PLANARIZE" at 11236.88,1207.82 h59
  text "XX MIL VIAS REQUIRE CONDUCTIVE FILL AND PLANARIZE" at 11244.88,1103.84 h60
  text "OUTER XX MIL TRACES REQUIRE 50 OHM SINGLE-ENDED IMPEDANCE" at 11243.89,940.46 h58
  text "LAYER 2 & 3 (INNER LAYERS) XX MIL WIDE, XX MIL SPACE / TRACES REQUIRE 100 OHM DIFFERENTIAL IMPEDANCE" at 11235.89,704.74 h60
  text ".Layer_Name" at 237.5,-1045.49 h60
M11 Gerber Information:
  lines w10: -631.5,-1117.17 5968.5,-1117.17 ; -631.5,-913.83 5970.5,-913.83 ; -631.5,-710.5 -631.5,-1320.5 3373.5,-1320.5 5970.5,-1320.5 5970.5,-710.5 -631,-710.5 -631,-1320.5 944.5,-1320.5 ; 1833.5,-1320.5 1833.5,-710.5 ; 3100.5,-913.83 3100.5,-710.5 ; 3940.5,-913.83 3940.5,-710.5 ; 4562.5,-1327 4562.5,-1124.17
  text "ALL ARTWORK VIEWED FROM TOP SIDE" at -568,-842.67 h60
  text "BOARD #:" at 1908.5,-842.67 h60
  text ".PRJ_Number" at 2454,-842.67 h60
  text "REV:" at 3298.5,-842.67 h60
  text ".PCB_Rev" at 3590,-842.67 h60
  text "SVN REV:" at 4136.5,-842.67 h60
  text ".VersionControl_RevNumber" at 4642.5,-842.67 h60
  text "LAYER NAME =" at -568,-1045.49 h60
  text "TID #:" at 1908.5,-1046 h60
  text ".TID" at 2454,-1046 h60
  text "PLOT NAME =" at -568,-1251.34 h60
  text ".plot_File_Name" at 237.5,-1251.34 h60
  text "GENERATED    :" at 1910.5,-1251.34 h60
  text ".Print_Date" at 2780,-1251.34 h60
  text ".Print_Time" at 3509,-1251.34 h60
  text "TEXAS INSTRUMENTS" at 4773.5,-1251.34 h60
M12 Stackup:
  drawing of 399 lines, arcs and shapes, not listed
  text "Layer" at 5840.88,6097.5 h60
  text "Name" at 6250.79,6097.5 h60
  text "Material" at 7180.54,6097.5 h60
  text "Thickness" at 8040.3,6097.5 h60
  text "Constant" at 8690.14,6097.5 h60
  text "Board Layer Stack" at 9260,6097.5 h60
  text "1" at 5840.88,5977.5 h60
  text "Top Overlay" at 6250.79,5977.5 h60
  text "2" at 5840.88,5857.5 h60
  text "Top Solder" at 6250.79,5857.5 h60
  text "Solder Resist" at 7180.54,5857.5 h60
  text "0.40mil" at 8040.3,5857.5 h60
  text "3.5" at 8690.14,5857.5 h60
  text "3" at 5840.88,5737.5 h60
  text "Top Layer" at 6250.79,5737.5 h60
  text "Copper" at 7180.54,5737.5 h60
  text "2.10mil" at 8040.3,5737.5 h60
  text "4" at 5840.88,5617.5 h60
  text "Dielectric 1" at 6250.79,5617.5 h60
  text "FR-4 High Tg" at 7180.54,5617.5 h60
  text "8.00mil" at 8040.3,5617.5 h60
  text "4.2" at 8690.14,5617.5 h60
  text "5" at 5840.88,5497.5 h60
  text "GND Layer 1" at 6250.79,5497.5 h60
  text "Copper" at 7180.54,5497.5 h60
  text "1.40mil" at 8040.3,5497.5 h60
  text "6" at 5840.88,5377.5 h60
  text "Dielectric 2" at 6250.79,5377.5 h60
  text "FR-4 High Tg" at 7180.54,5377.5 h60
  text "14.50mil" at 8040.3,5377.5 h60
  text "4.2" at 8690.14,5377.5 h60
  text "7" at 5840.88,5257.5 h60
  text "Signal Layer 1" at 6250.79,5257.5 h60
  text "Copper" at 7180.54,5257.5 h60
  text "1.40mil" at 8040.3,5257.5 h60
  text "8" at 5840.88,5137.5 h60
  text "Dielectric 3" at 6250.79,5137.5 h60
  text "FR-4 High Tg" at 7180.54,5137.5 h60
  text "8.00mil" at 8040.3,5137.5 h60
  text "4.2" at 8690.14,5137.5 h60
  text "9" at 5840.88,5017.5 h60
  text "GND Layer 2" at 6250.79,5017.5 h60
  text "Copper" at 7180.54,5017.5 h60
  text "1.40mil" at 8040.3,5017.5 h60
  text "10" at 5840.88,4897.5 h60
  text "Dielectric4" at 6250.79,4897.5 h60
  text "FR-4 High Tg" at 7180.54,4897.5 h60
  text "14.50mil" at 8040.3,4897.5 h60
  text "4.2" at 8690.14,4897.5 h60
  text "11" at 5840.88,4777.5 h60
  text "Signal Layer3" at 6250.79,4777.5 h60
  text "Copper" at 7180.54,4777.5 h60
  text "1.40mil" at 8040.3,4777.5 h60
  text "12" at 5840.88,4657.5 h60
  text "Dielectric6" at 6250.79,4657.5 h60
  text "FR-4 High Tg" at 7180.54,4657.5 h60
  text "8.00mil" at 8040.3,4657.5 h60
  text "4.2" at 8690.14,4657.5 h60
  text "13" at 5840.88,4537.5 h60
  text "Bottom Layer" at 6250.79,4537.5 h60
  text "Copper" at 7180.54,4537.5 h60
  text "2.10mil" at 8040.3,4537.5 h60
  text "14" at 5840.88,4417.5 h60
  text "Bottom Solder" at 6250.79,4417.5 h60
  text "Solder Resist" at 7180.54,4417.5 h60
  text "0.40mil" at 8040.3,4417.5 h60
  text "3.5" at 8690.14,4417.5 h60
  text "15" at 5840.88,4297.5 h60
  text "Bottom Overlay" at 6250.79,4297.5 h60
  text ".Layer_Name" at 237.5,-1045.49 h60
M13 Component Bodies Top:
  text ".Layer_Name" at 237.5,-1045.49 h60
M14 Component Bodies Bottom:
  text ".Layer_Name" at 237.5,-1045.49 h60
M15 Courtyards Top:
  text ".Layer_Name" at 237.5,-1045.49 h60
M16 Courtyards Bottom:
  text ".Layer_Name" at 237.5,-1045.49 h60
Drill Drawing:
  circle w10: c4024.22,1705.04 r27.63
  lines w10: 3996.59,1553.1 4051.84,1553.1 4051.84,1608.35 3996.59,1608.35 3996.59,1553.1 ; 3996.59,1815.55 4010.4,1815.55 4010.4,1801.74 4038.03,1801.74 4038.03,1815.55 4051.84,1815.55 4051.84,1843.18 4038.03,1843.18 4038.03,1856.99 4010.4,1856.99 4010.4,1843.18 3996.59,1843.18 3996.59,1815.55 ; 3996.59,1926.06 4051.84,1926.06 4051.84,1981.31 3996.59,1981.31 3996.59,1926.06 ; 3996.59,2050.38 4024.22,2064.19 4051.84,2050.38 4038.03,2078 4051.84,2105.63 4024.22,2091.82 3996.59,2105.63 4010.4,2078 3996.59,2050.38 ; 3996.59,2188.51 4010.4,2188.51 4024.22,2174.7 4038.03,2188.51 4051.84,2188.51 4038.03,2202.32 4051.84,2216.14 4038.03,2216.14 4024.22,2229.95 4010.4,2216.14 3996.59,2216.14 4010.4,2202.32 3996.59,2188.51 ; 3996.59,2354.27 4051.84,2354.27 4024.22,2299.02 3996.59,2354.27 ; 3996.59,2450.96 4024.22,2423.34 4051.84,2450.96 4024.22,2478.59 3996.59,2450.96 ; 3996.59,2547.66 3996.59,2561.47 4010.4,2575.28 3996.59,2589.1 3996.59,2602.91 4010.4,2602.91 4024.22,2589.1 4038.03,2602.91 4051.84,2602.91 4051.84,2589.1 4038.03,2575.28 4051.84,2561.47 4051.84,2547.66 4038.03,2547.66 4024.22,2561.47 4010.4,2547.66 3996.59,2547.66 ; 4007.64,1564.15 4040.79,1564.15 4040.79,1597.3 4007.64,1597.3 4007.64,1564.15
  lines w12: 3946.5,1515.8 7177.99,1515.8 ; 3946.5,2634.68 7177.99,2634.68 ; 4284.36,1391.48 4284.36,2759 ; 4616.36,1391.48 4616.36,2759 ; 5252.93,1391.48 5252.93,2759 ; 5512.07,1391.48 5512.07,2759 ; 5887.22,1391.48 5887.22,2759 ; 6611.55,1391.48 6611.55,2759 ; 3946.5,1391.48 7177.99,1391.48 7177.99,2759 3946.5,2759 3946.5,1391.48
  text "Symbol" at 4021.09,2671.98 h72
  text "Quantity" at 4321.66,2671.98 h72
  text "Finished Hole Size" at 4653.66,2671.98 h72
  text "Plated" at 5290.22,2671.98 h72
  text "Hole Type" at 5549.36,2671.98 h72
  text "Drill Layer Pair" at 5924.52,2671.98 h72
  text "Hole Tolerance" at 6648.85,2671.98 h72
  text "6" at 4321.66,2547.66 h60
  text "7.87mil (0.200mm)" at 4653.66,2547.66 h60
  text "PTH" at 5290.22,2547.66 h60
  text "Round" at 5549.36,2547.66 h60
  text "Top Layer - Bottom Layer" at 5924.52,2547.66 h60
  text "561" at 4321.66,2423.34 h60
  text "8.00mil (0.203mm)" at 4653.66,2423.34 h60
  text "PTH" at 5290.22,2423.34 h60
  text "Round" at 5549.36,2423.34 h60
  text "Top Layer - Bottom Layer" at 5924.52,2423.34 h60
  text "116" at 4321.66,2299.02 h60
  text "16.00mil (0.406mm)" at 4653.66,2299.02 h60
  text "PTH" at 5290.22,2299.02 h60
  text "Round" at 5549.36,2299.02 h60
  text "Top Layer - Bottom Layer" at 5924.52,2299.02 h60
  text "5" at 4321.66,2174.7 h60
  text "40.00mil (1.016mm)" at 4653.66,2174.7 h60
  text "PTH" at 5290.22,2174.7 h60
  text "Round" at 5549.36,2174.7 h60
  text "Top Layer - Bottom Layer" at 5924.52,2174.7 h60
  text "4" at 4321.66,2050.38 h60
  text "51.18mil (1.300mm)" at 4653.66,2050.38 h60
  text "PTH" at 5290.22,2050.38 h60
  text "Round" at 5549.36,2050.38 h60
  text "Top Layer - Bottom Layer" at 5924.52,2050.38 h60
  text "6" at 4321.66,1926.06 h60
  text "63.00mil (1.600mm)" at 4653.66,1926.06 h60
  text "PTH" at 5290.22,1926.06 h60
  text "Round" at 5549.36,1926.06 h60
  text "Top Layer - Bottom Layer" at 5924.52,1926.06 h60
  text "4" at 4321.66,1801.74 h60
  text "125.98mil (3.200mm)" at 4653.66,1801.74 h60
  text "PTH" at 5290.22,1801.74 h60
  text "Round" at 5549.36,1801.74 h60
  text "Top Layer - Bottom Layer" at 5924.52,1801.74 h60
  text "2" at 4321.66,1677.42 h60
  text "254.00mil (6.452mm)" at 4653.66,1677.42 h60
  text "PTH" at 5290.22,1677.42 h60
  text "Round" at 5549.36,1677.42 h60
  text "Top Layer - Bottom Layer" at 5924.52,1677.42 h60
  text "2" at 4321.66,1553.1 h60
  text "270.00mil (6.858mm)" at 4653.66,1553.1 h60
  text "PTH" at 5290.22,1553.1 h60
  text "Round" at 5549.36,1553.1 h60
  text "Top Layer - Bottom Layer" at 5924.52,1553.1 h60
  text "706 Total" at 4321.66,1428.78 h60
  text ".Layer_Name" at 237.5,-1045.49 h60
M17 Embedded Cavity:
  text ".Layer_Name" at 237.5,-1045.49 h60
M18 Embedded Assembly:
  text ".Layer_Name" at 237.5,-1045.49 h60
M19 Embedded Keepout:
  text ".Layer_Name" at 237.5,-1045.49 h60

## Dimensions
0,0 to 0,2800 on M2 Board Dimensions
0,0 to 3300,0 on M2 Board Dimensions
-339.5,-587 to 660.5,-587 on M2 Board Dimensions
